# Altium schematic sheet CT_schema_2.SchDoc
size 313 x 185 mm
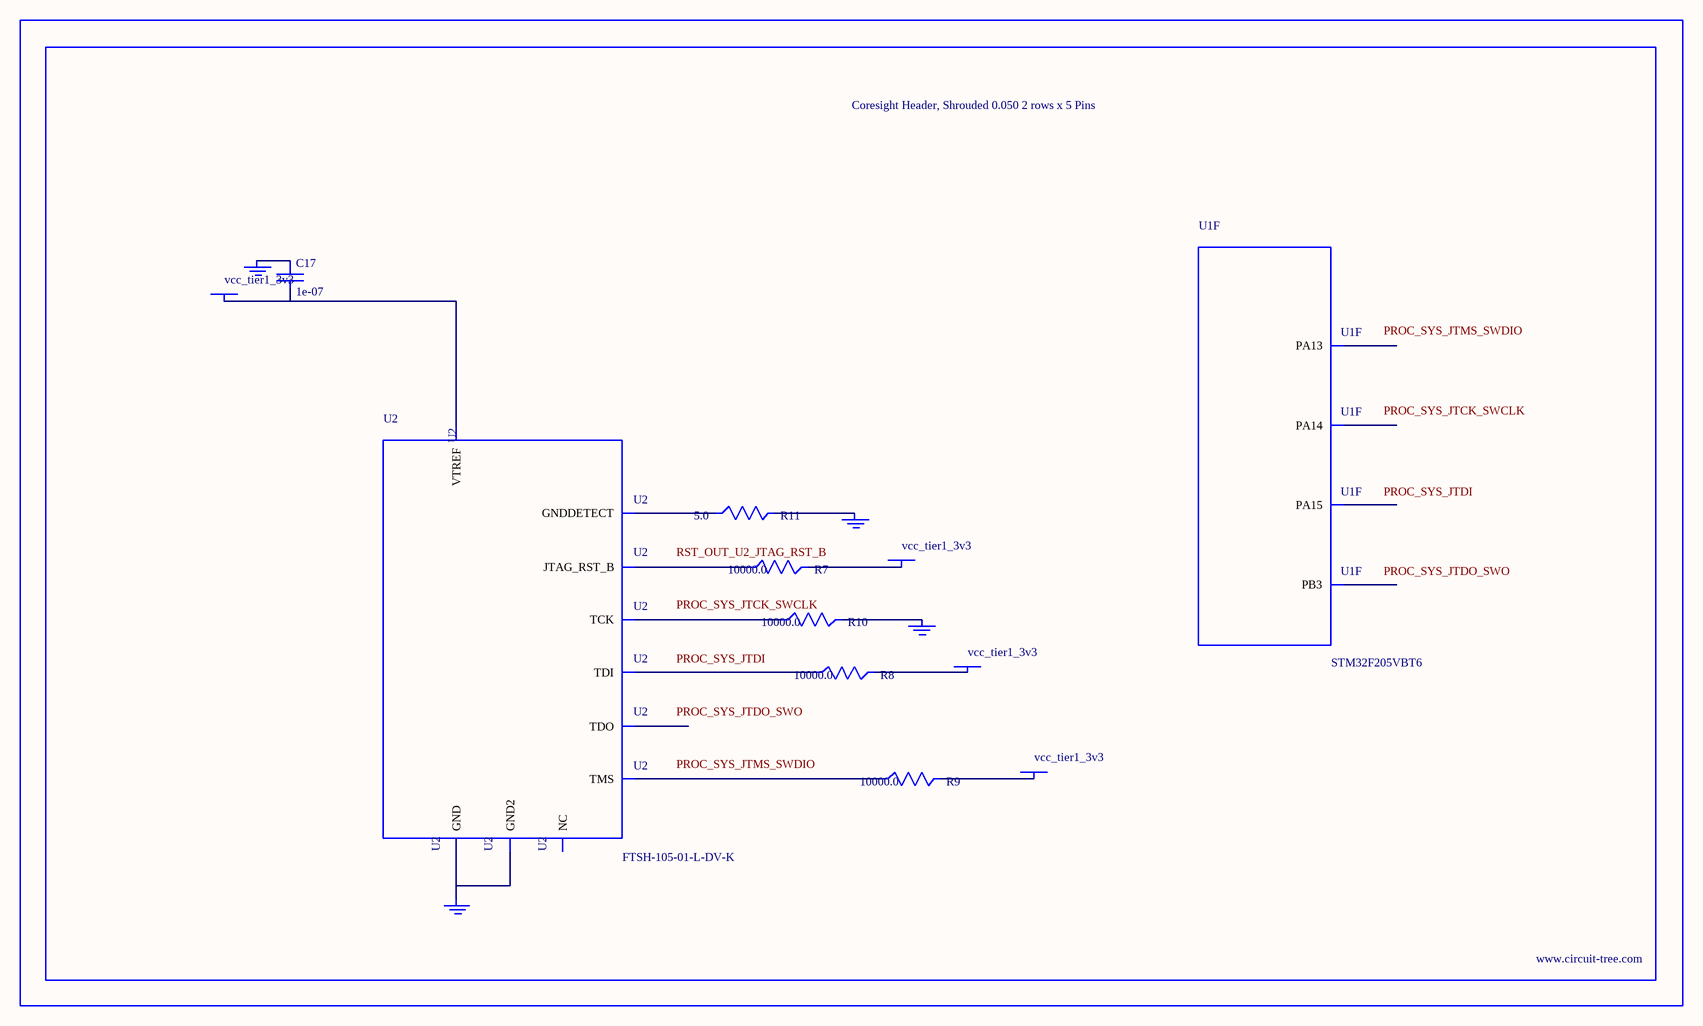
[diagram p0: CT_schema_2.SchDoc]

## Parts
BORDER1  (no value)
C17  1e-07  [C0402]
GND_INSTANCE_1_0  (no value)
GND_INSTANCE_1_1  (no value)
GND_INSTANCE_1_2  (no value)
GND_INSTANCE_1_3  (no value)
POWER_INSTANCE_1_0  vcc_tier1_3v3
POWER_INSTANCE_1_1  vcc_tier1_3v3
POWER_INSTANCE_1_2  vcc_tier1_3v3
POWER_INSTANCE_1_3  vcc_tier1_3v3
R7  10000.0  [R0603]
R8  10000.0  [R0603]
R9  10000.0  [R0603]
R10  10000.0  [R0603]
R11  5.0  [R0603]
U1  STM32F205VBT6  [LQFP100]  (part F of 8)
U2  FTSH-105-01-L-DV-K  [SAMTEC_FTSH-105-01-L-DV-K]

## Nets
NetC17_1: C17.1 GND_INSTANCE_1_0.0(GND)
NetC17_2: C17.2 POWER_INSTANCE_1_0.0(PWR) U2.1(VTREF)
NetGND_INSTANCE_1_1_0: GND_INSTANCE_1_1.0(GND) R10.2
NetGND_INSTANCE_1_2_0: GND_INSTANCE_1_2.0(GND) R11.2
NetGND_INSTANCE_1_3_0: GND_INSTANCE_1_3.0(GND) U2.3(GND) U2.5(GND2)
NetPOWER_INSTANCE_1_1_0: POWER_INSTANCE_1_1.0(PWR) R9.2
NetPOWER_INSTANCE_1_2_0: POWER_INSTANCE_1_2.0(PWR) R8.2
NetPOWER_INSTANCE_1_3_0: POWER_INSTANCE_1_3.0(PWR) R7.2
NetR7_1: R7.1 U2.10(JTAG_RST_B)
NetR8_1: R8.1 U2.8(TDI)
NetR9_1: R9.1 U2.2(TMS)
NetR10_1: R10.1 U2.4(TCK)
NetR11_1: R11.1 U2.9(GNDDETECT)

Not connected (* = marked no-connect by the designer): U1 72(PA13) 76(PA14) 77(PA15) 89(PB3); U2 6(TDO) 7(NC)

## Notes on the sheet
- Labels drawn without touching a wire or pin: PROC_SYS_JTCK_SWCLK, PROC_SYS_JTDI, PROC_SYS_JTDO_SWO, PROC_SYS_JTMS_SWDIO, RST_OUT_U2_JTAG_RST_B

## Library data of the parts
BORDER1 = BORDER_PAGE1
C17 = C0402C104K3RACTU
GND_INSTANCE_1_0-GND_INSTANCE_1_3 = GND
POWER_INSTANCE_1_0-POWER_INSTANCE_1_3 = PWR
R7-R10 = RC0603JR-0710KL
R11 = ERJ-3GEYJ5R1V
